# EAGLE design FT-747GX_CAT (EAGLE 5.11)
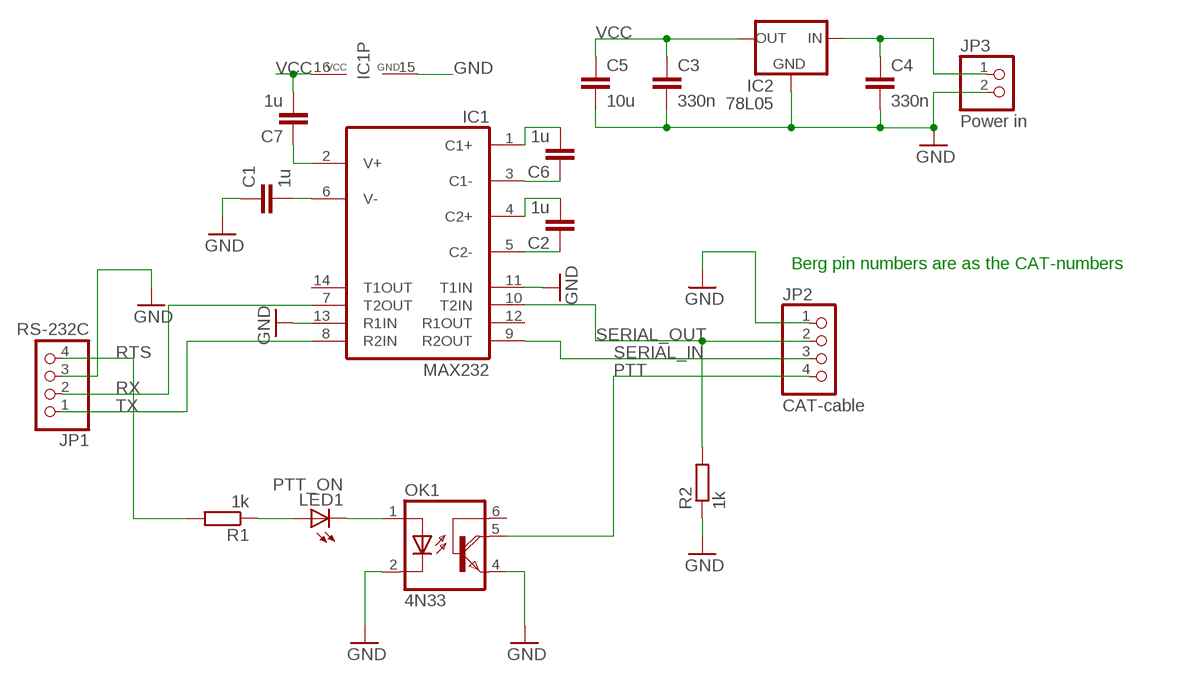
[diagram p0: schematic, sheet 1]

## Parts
C1  1u  C-EU050-024X044  [C050-024X044]
C2  1u  C-EU050-024X044  [C050-024X044]
C3  330n  C-EU050-024X044  [C050-024X044]
C4  330n  C-EU050-024X044  [C050-024X044]
C5  10u  C-EU050-075X075  [C050-075X075]
C6  1u  C-EU050-024X044  [C050-024X044]
C7  1u  C-EU050-024X044  [C050-024X044]
IC1  MAX232  [DIL16]
IC2  78L05  78LXX  [78LXX]
JP1  RS-232C  PINHD-1X4/90  [1X04/90]
JP2  CAT-cable  PINHD-1X4/90  [1X04/90]
JP3  Power in  PINHD-1X2/90  [1X02/90]
LED1  PTT_ON  LED3MM  [LED3MM]
OK1  4N33  [DIL06]
R1  1k  R-EU_0204/7  [0204/7]
R2  1k  R-EU_0204/7  [0204/7]

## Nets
GND: C1.1 C3.2 C4.2 C5.2 IC1.11(T1IN) IC1.13(R1IN) IC1.15(GND) IC2.GND JP1.3 JP2.1 JP3.2 OK1.2(C) OK1.4(E) R2.1
N$1: C1.2 IC1.6(V-)
N$2: C7.1 IC1.2(V+)
N$3: C6.1 IC1.3(C1-)
N$4: C6.2 IC1.1(C1+)
N$5: LED1.A R1.1
N$6: LED1.K(C) OK1.1(A)
N$7: C2.2 IC1.4(C2+)
N$8: C2.1 IC1.5(C2-)
N$10: C4.1 IC2.IN JP3.1
PTT: JP2.4 OK1.5(COL)
RTS: JP1.4 R1.2
RX: IC1.7(T2OUT) JP1.2
SERIAL_IN: IC1.9(R2OUT) JP2.3
SERIAL_OUT: IC1.10(T2IN) JP2.2 R2.2
TX: IC1.8(R2IN) JP1.1
VCC: C3.1 C5.1 C7.2 IC1.16(VCC) IC2.OUT
Unconnected: IC1.12(R1OUT) IC1.14(T1OUT) OK1.6(B)

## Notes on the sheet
- Berg pin numbers are as the CAT-numbers

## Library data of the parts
C1-C7 = rcl:C-EU: CAPACITOR, European symbol
IC1 = maxim:MAX232: RS232 TRANSEIVER; MF: MAXIM; MPN: MAX232ACPE+; OC_FARNELL: 9723773; OC_NEWARK: 68K4544
IC2 = v-reg:78LXX: VOLTAGE REGULATOR
JP1 JP2 = pinhead:PINHD-1X4: PIN HEADER
JP3 = pinhead:PINHD-1X2: PIN HEADER
LED1 = led:LED: LED
OK1 = optocoupler:4N33: MOTOROLA OPTO COUPLER; MF: VISHAY/TELEFUNKEN; MPN: 4N33; OC_FARNELL: 1469601; OC_NEWARK: 88K1390
R1 R2 = rcl:R-EU_: RESISTOR, European symbol

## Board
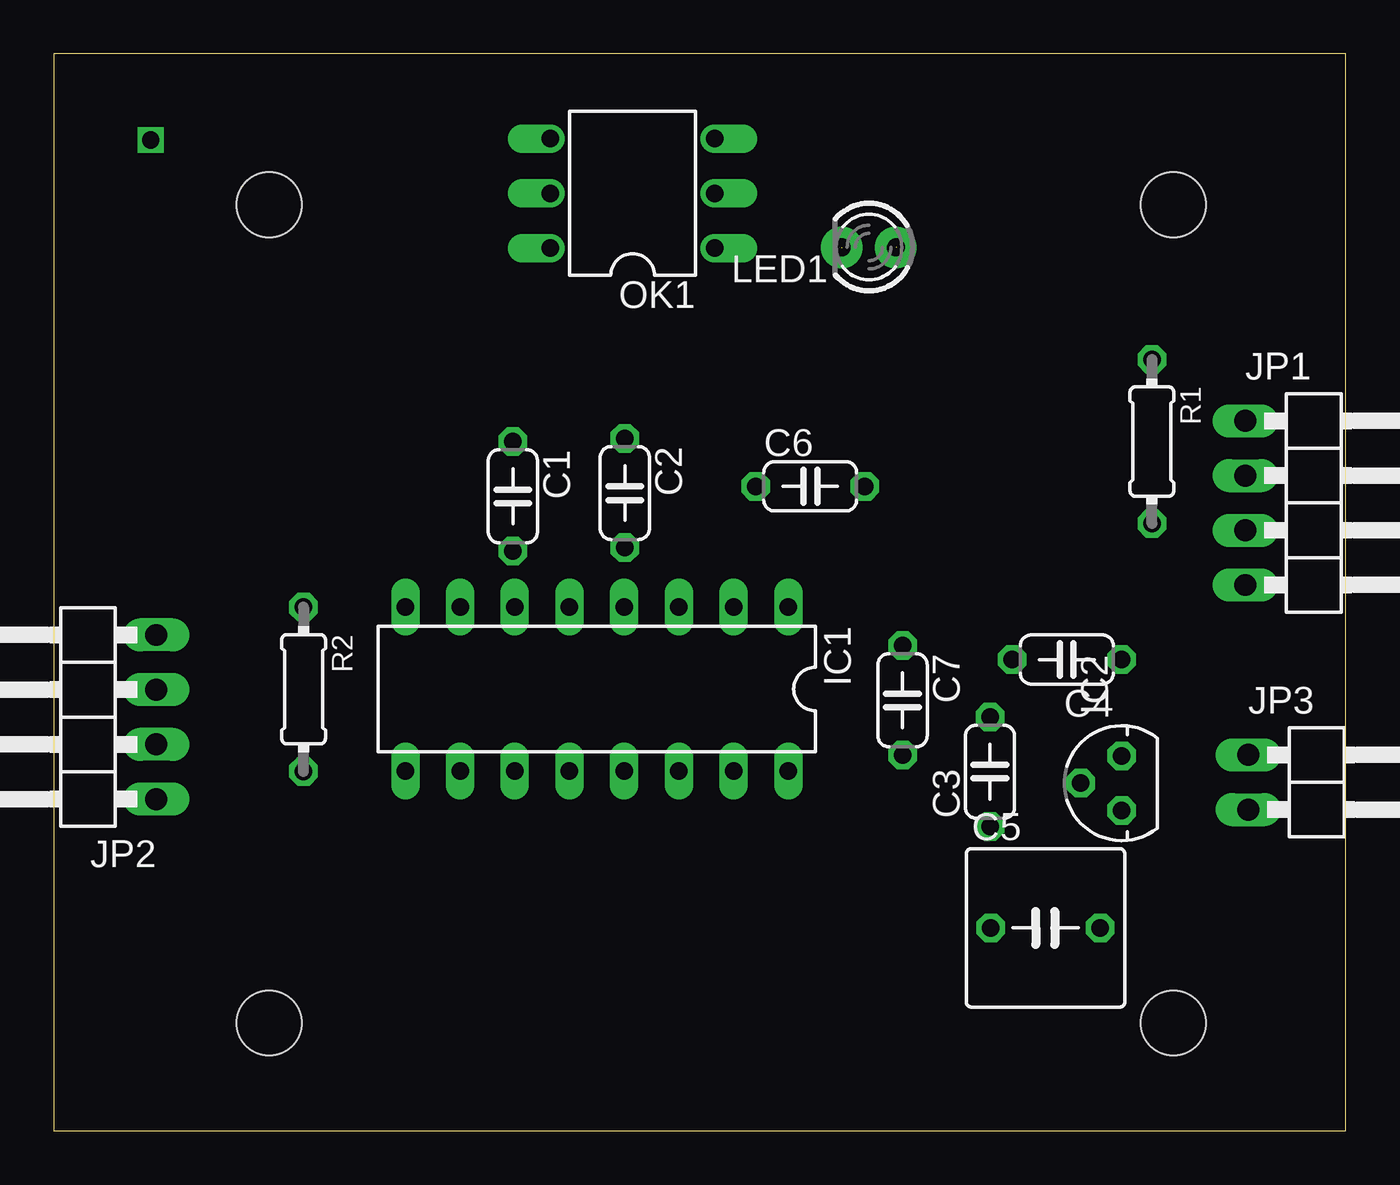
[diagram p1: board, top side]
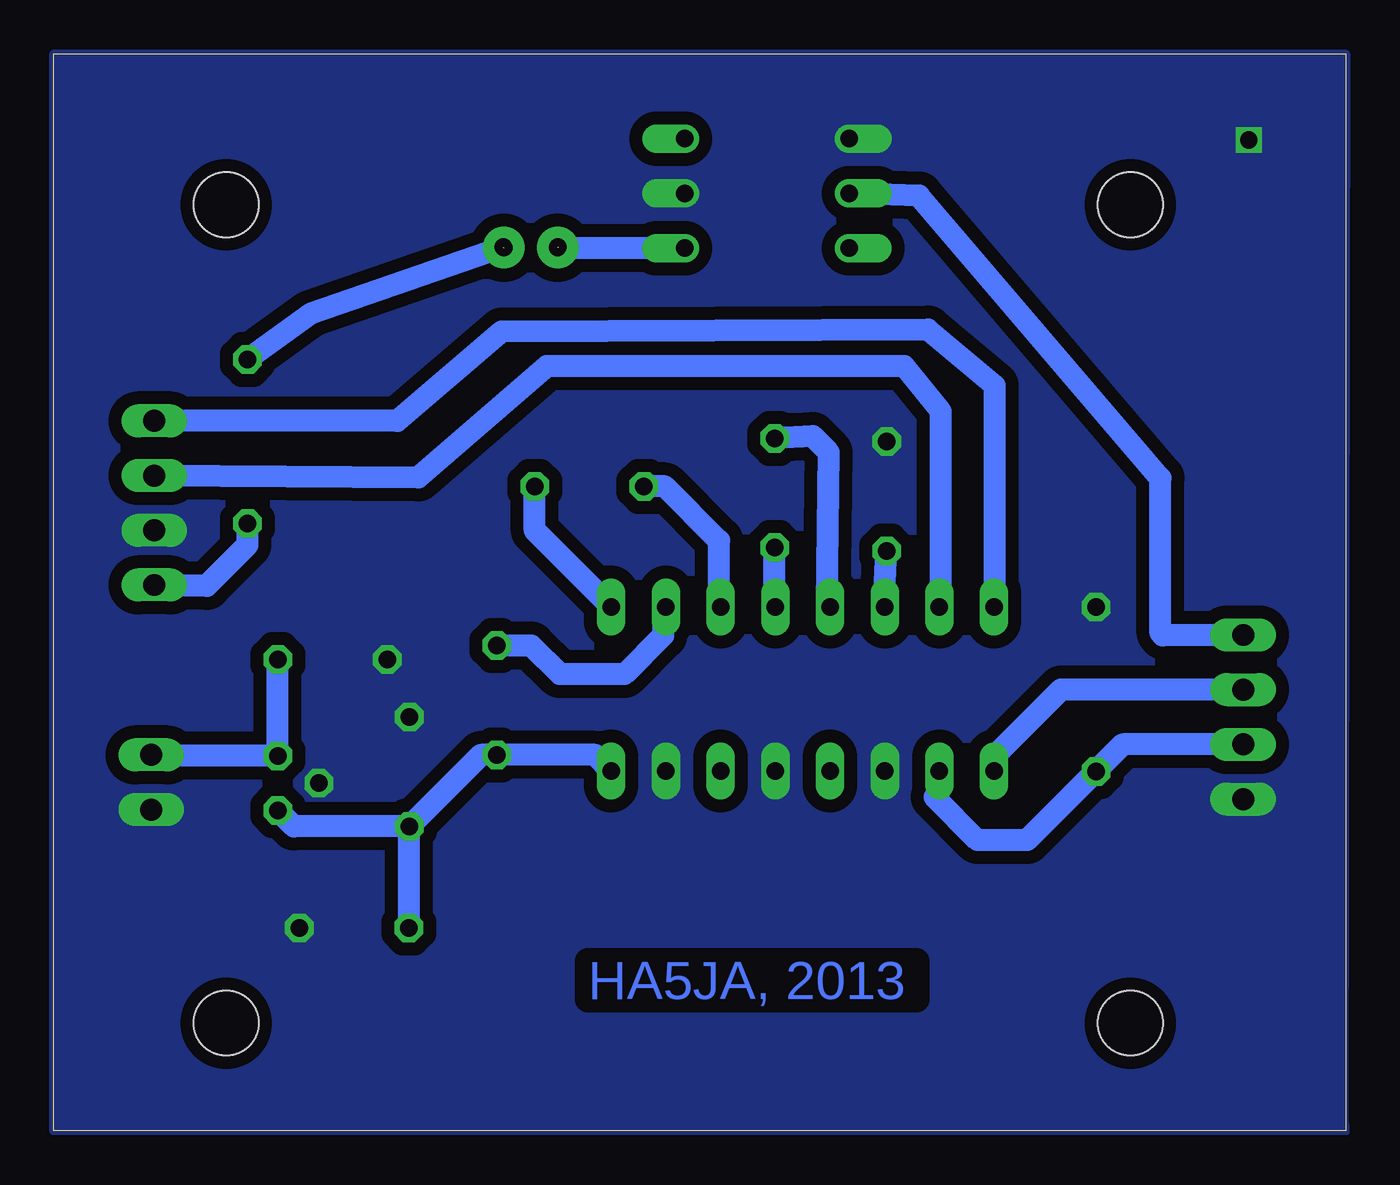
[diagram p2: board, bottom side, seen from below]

Size 60 x 50 mm. Coordinates in mm from the lower left corner, seen from the top.
Outline: 0,0 60,0 60,50 0,50 0,0
Copper layers (1*16): Top 0.035mm / dielectric 1.5mm / Bottom 0.035mm
Design rules "default *": minimum track width 10mil, minimum drill 24mil, track to track 8mil, track to pad 8mil, pad to pad 8mil, via to via 8mil, smd to smd 8mil, copper to edge 0mil, drill to drill 8mil, minimum pad ring 10mil, minimum via ring 8mil, stop-mask expansion 4mil, vias tented up to drill 0mil, thermal gap 10mil
Holes 3 mm at 10,5 10,43 52,43 52,5

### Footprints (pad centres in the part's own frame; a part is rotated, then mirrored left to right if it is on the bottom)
C050-024X044 = drill 0.813 octagon: 1 -2.54,0; 2 2.54,0
C050-075X075 = drill 0.813 octagon: 1 -2.54,0; 2 2.54,0
DIL16 = drill 0.813 long: 1 -8.89,-3.81; 2 -6.35,-3.81; 3 -3.81,-3.81; 4 -1.27,-3.81; 5 1.27,-3.81; 6 3.81,-3.81; 7 6.35,-3.81; 8 8.89,-3.81; 9 8.89,3.81; 10 6.35,3.81; 11 3.81,3.81; 12 1.27,3.81; 13 -1.27,3.81; 14 -3.81,3.81; 15 -6.35,3.81; 16 -8.89,3.81
78LXX = drill 0.813 octagon: GND 0,1.905; IN 1.27,0; OUT -1.27,0
1X04/90 = drill 1.016 long: 1 -3.81,-3.81; 2 -1.27,-3.81; 3 1.27,-3.81; 4 3.81,-3.81
1X02/90 = drill 1.016 long: 1 -1.27,-3.81; 2 1.27,-3.81
LED3MM = drill 0.813 octagon: A -1.27,0; K 1.27,0
DIL06 = drill 0.813 offset: 1 -2.54,-3.81; 2 0,-3.81; 3 2.54,-3.81; 4 2.54,3.81; 5 0,3.81; 6 -2.54,3.81
0204/7 = drill 0.813 octagon: 1 -3.81,0; 2 3.81,0

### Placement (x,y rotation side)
C1  21.32,29.46 270 top
C2  26.52,29.61 270 top
C3  43.48,16.67 90 top
C4  47.05,21.88 180 top
C5  46.06,9.42 0 top
C6  35.13,29.92 0 top
C7  39.42,19.99 270 top
IC1  25.22,20.51 180 top
IC2  49.6,16.14 90 top
JP1  59.15,29.15 270 top
JP2  0.95,19.21 90 top
JP3  59.29,16.18 270 top
LED1  37.86,41.03 180 top
OK1  26.88,43.52 90 top
R1  51,32 270 top
R2  11.6,20.5 270 top

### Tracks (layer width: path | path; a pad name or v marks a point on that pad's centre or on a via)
GND  (via drill 0.8)
  other vias: 4.5,46
  pour Bottom (isolate 0.61, no thermals): 0,0 60,0 60,50 0,50 0.1,0.4
N$1
  Bottom 1.016: C1.2 21.42,25.02 21.4,25 IC1.6
N$2
  Bottom 1.016: C7.1 37.83,22.53 36.5,21.2 33.5,21.2 31.7,23 31.7,24.19 IC1.2
N$3
  Bottom 1.016: C6.1 31.62,29.92 29.1,27.4 29.1,24.39 IC1.3
N$4
  Bottom 1.016: C6.2 37.67,27.88 IC1.1
N$5  (via drill 0.8 pad 1.93)  (1 unrouted)
  Bottom 1.016: LED1.A 48.08,37.93 R1.1
  other vias: 39.1,41
N$6  (via drill 0.8 pad 1.93)  (1 unrouted)
  Bottom 1.016: OK1.1 36.54,40.98 LED1.K
  other vias: 36.6,41
N$7
  Bottom 1.016: C2.2 26.52,24.35 IC1.4
N$8
  Bottom 1.016: C2.1 24.75,32.25 24,31.5 24.1,24.47 IC1.5
N$10
  Bottom 1.016: JP3.1 55.44,17.41 IC2.IN C4.1
PTT
  Bottom 1.016: OK1.5 19.82,43.42 8.6,30.3 8.6,23.1 8.5,23 4.78,23 JP2.4
RTS
  Bottom 1.016: R1.2 51,27.2 52.9,25.3 55.3,25.3 JP1.4
RX
  Bottom 1.016: JP1.2 43.08,30.32 37.1,35.5 20.5,35.5 18.8,33.4 18.8,24.39 IC1.7
SERIAL_IN
  Bottom 0.406: 16.5,17.2 16.5,16.87 IC1.9
  Bottom 1.016: JP2.3 13.22,20.48 16.5,17.2
SERIAL_OUT
  Bottom 0.406: R2.2 | 19.1,15.5 19.1,16.47 IC1.10
  Bottom 1.016: JP2.2 10.35,17.94 R2.2 | R2.2 14.8,13.5 17.1,13.5 19.1,15.5
TX
  Bottom 1.016: JP1.1 44.04,32.96 39.2,37.1 19.4,37.2 16.3,34.6 16.3,24.35 IC1.8
VCC
  Bottom 1.016: IC1.16 34.86,17.45 C7.2 40.16,17.45 C3.1 | C5.1 43.52,14.09 C3.1 | C3.1 48.86,14.13 IC2.OUT

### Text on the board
Bottom: HA5JA, 2013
